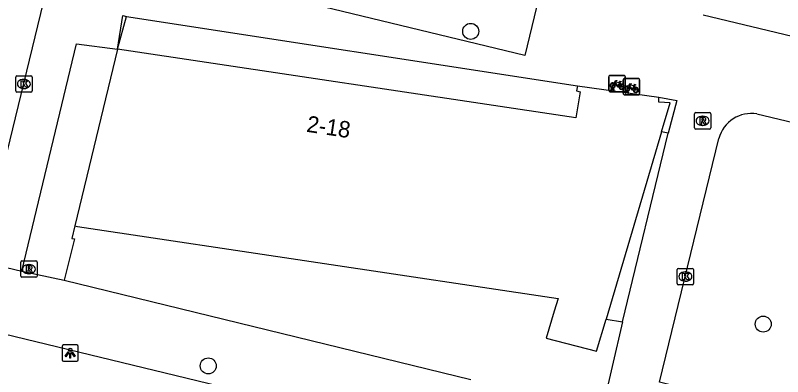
# Model space of a CAD drawing. Extents: x 162812 to 163818, y 381639 to 382470.
# Drawn here: x 163269.18 to 163316.1, y 382171.85 to 382193.93 of the extents above; entities that cross this region are included whole.
import ezdxf

# ---------------------------------------------------------------- set-up
doc = ezdxf.new("R2010")
doc.units = 0
for name, color, linetype in [('IMGEO_Boom', 7, 'Continuous'), ('IMGEO_Fietsenrek', 7, 'Continuous'), ('IMGEO_Groenvoorziening', 7, 'Continuous'), ('IMGEO_Kolk', 7, 'Continuous'), ('IMGEO_Lichtpunt', 7, 'Continuous'), ('IMGEO_Pand', 7, 'Continuous'), ('IMGEO_Pand_nummerreeks', 7, 'Continuous'), ('IMGEO_Pand_overbouw', 7, 'Continuous'), ('IMGEO_Rijbaan_lokaal_open', 7, 'Continuous'), ('IMGEO_Rioolput', 7, 'Continuous'), ('IMGEO_Voetpad_open', 7, 'Continuous')]:
    doc.layers.add(name, color=color, linetype=linetype)

msp = doc.modelspace()

# ---------------------------------------------------------------- linework, layer by layer
at = {"layer": 'IMGEO_Boom'}
for centre in [(163297.026, 382192.949), (163314.913, 382175.057), (163280.98, 382172.501)]:
    msp.add_circle(centre, 0.489, dxfattribs=at)
at = {"layer": 'IMGEO_Fietsenrek'}
for p, q in [((163305.476, 382189.335), (163305.476, 382190.176)), ((163305.476, 382190.176), (163305.476, 382189.335)), ((163305.551, 382190.26), (163306.392, 382190.26)), ((163306.392, 382190.26), (163305.551, 382190.26)), ((163306.433, 382190.066), (163307.274, 382190.066)), ((163307.274, 382190.066), (163306.433, 382190.066)), ((163306.476, 382190.185), (163306.476, 382189.344)), ((163306.476, 382189.344), (163306.476, 382190.185)), ((163306.163, 382189.809), (163306.199, 382189.714)), ((163306.358, 382189.141), (163306.358, 382189.982)), ((163306.358, 382189.982), (163306.358, 382189.141)), ((163307.045, 382189.615), (163307.081, 382189.52)), ((163307.358, 382189.991), (163307.358, 382189.15)), ((163307.358, 382189.15), (163307.358, 382189.991)), ((163306.401, 382189.26), (163305.56, 382189.26)), ((163305.56, 382189.26), (163306.401, 382189.26)), ((163305.603, 382189.344), (163305.642, 382189.504)), ((163305.637, 382189.344), (163305.603, 382189.344)), ((163305.672, 382189.492), (163305.637, 382189.344)), ((163305.714, 382189.516), (163305.713, 382189.52)), ((163305.755, 382189.344), (163305.721, 382189.486)), ((163305.745, 382189.527), (163305.746, 382189.52)), ((163305.753, 382189.49), (163305.788, 382189.344)), ((163305.788, 382189.344), (163305.755, 382189.344)), ((163306.485, 382189.15), (163306.524, 382189.31)), ((163306.519, 382189.15), (163306.485, 382189.15)), ((163306.554, 382189.298), (163306.519, 382189.15)), ((163306.596, 382189.322), (163306.595, 382189.326)), ((163306.637, 382189.15), (163306.603, 382189.292)), ((163306.627, 382189.333), (163306.628, 382189.326)), ((163306.635, 382189.296), (163306.67, 382189.15)), ((163306.67, 382189.15), (163306.637, 382189.15)), ((163307.283, 382189.066), (163306.442, 382189.066)), ((163306.442, 382189.066), (163307.283, 382189.066))]:
    msp.add_line(p, q, dxfattribs=at)
for points in [[(163305.81, 382189.734), (163305.758, 382189.644), (163305.718, 382189.619), (163305.719, 382189.666), (163305.774, 382189.76)], [(163305.789, 382189.786), (163305.884, 382189.95), (163305.97, 382189.936), (163305.972, 382189.927), (163305.916, 382189.916), (163305.889, 382189.871), (163306.145, 382189.83)], [(163306.085, 382189.542), (163306.035, 382189.542), (163305.844, 382189.793), (163305.825, 382189.761)], [(163306.132, 382189.805), (163305.875, 382189.846), (163305.858, 382189.817), (163306.025, 382189.597), (163306.132, 382189.805)], [(163306.18, 382189.707), (163306.15, 382189.784), (163306.041, 382189.566), (163306.084, 382189.566)], [(163306.114, 382189.566), (163306.234, 382189.565), (163306.19, 382189.679)], [(163306.21, 382189.686), (163306.265, 382189.541), (163306.115, 382189.541)], [(163306.145, 382189.83), (163306.17, 382189.879), (163306.164, 382189.883), (163306.141, 382189.887), (163306.129, 382189.894), (163306.128, 382189.897), (163306.13, 382189.902), (163306.225, 382189.887), (163306.227, 382189.877), (163306.217, 382189.864), (163306.205, 382189.858), (163306.191, 382189.864), (163306.163, 382189.809)], [(163306.692, 382189.54), (163306.64, 382189.45), (163306.6, 382189.425), (163306.601, 382189.472), (163306.656, 382189.566)], [(163306.671, 382189.592), (163306.766, 382189.756), (163306.852, 382189.742), (163306.854, 382189.733), (163306.798, 382189.722), (163306.771, 382189.677), (163307.027, 382189.636)], [(163306.967, 382189.348), (163306.917, 382189.348), (163306.726, 382189.599), (163306.707, 382189.567)], [(163307.014, 382189.611), (163306.757, 382189.652), (163306.74, 382189.623), (163306.907, 382189.403), (163307.014, 382189.611)], [(163307.062, 382189.513), (163307.032, 382189.59), (163306.923, 382189.372), (163306.966, 382189.372)], [(163307.027, 382189.636), (163307.052, 382189.685), (163307.046, 382189.689), (163307.023, 382189.693), (163307.011, 382189.7), (163307.01, 382189.703), (163307.012, 382189.708), (163307.107, 382189.693), (163307.109, 382189.683), (163307.099, 382189.67), (163307.087, 382189.664), (163307.073, 382189.67), (163307.045, 382189.615)], [(163306.996, 382189.372), (163307.116, 382189.371), (163307.072, 382189.485)], [(163307.092, 382189.492), (163307.147, 382189.347), (163306.997, 382189.347)]]:
    msp.add_lwpolyline(points, dxfattribs=at)
for centre, radius, start, end in [((163305.554, 382190.182), 0.0779, 92.4484, 184.2845), ((163305.554, 382190.182), 0.0779, 92.4484, 184.2845), ((163306.436, 382189.988), 0.0779, 92.4484, 184.2845), ((163306.436, 382189.988), 0.0779, 92.4484, 184.2845), ((163306.398, 382190.182), 0.0779, 2.4484, 94.2845), ((163306.398, 382190.182), 0.0779, 2.4484, 94.2845), ((163307.28, 382189.988), 0.0779, 2.4484, 94.2845), ((163307.28, 382189.988), 0.0779, 2.4484, 94.2845), ((163305.716, 382189.645), 0.159, 62.6766, 242.1369), ((163305.716, 382189.645), 0.129, 63.3192, 238.903), ((163305.696, 382189.516), 0.0499, 12.8025, 158.6934), ((163305.716, 382189.645), 0.129, 283.6043, 43.4302), ((163305.716, 382189.645), 0.159, 283.5766, 46.6042), ((163306.243, 382189.561), 0.159, 113.3408, 178.3217), ((163306.243, 382189.561), 0.159, 187.0065, 105.7708), ((163306.243, 382189.561), 0.129, 113.923, 177.9556), ((163306.243, 382189.561), 0.129, 188.6715, 104.5883), ((163306.598, 382189.451), 0.159, 62.6766, 242.1369), ((163306.598, 382189.451), 0.129, 63.3192, 238.903), ((163306.598, 382189.451), 0.129, 283.6043, 43.4302), ((163306.598, 382189.451), 0.159, 283.5766, 46.6042), ((163305.554, 382189.338), 0.0779, 182.4484, 274.2845), ((163305.554, 382189.338), 0.0779, 182.4484, 274.2845), ((163305.716, 382189.645), 0.159, 253.9967, 271.7867), ((163305.696, 382189.516), 0.0174, 12.8025, 163.4502), ((163305.716, 382189.645), 0.129, 253.415, 269.0204), ((163306.436, 382189.144), 0.0779, 182.4484, 274.2845), ((163306.436, 382189.144), 0.0779, 182.4484, 274.2845), ((163306.398, 382189.338), 0.0779, 272.4484, 4.2845), ((163306.398, 382189.338), 0.0779, 272.4484, 4.2845), ((163306.578, 382189.322), 0.0499, 12.8025, 158.6934), ((163306.598, 382189.451), 0.159, 253.9967, 271.7867), ((163306.578, 382189.322), 0.0174, 12.8025, 163.4502), ((163306.598, 382189.451), 0.129, 253.415, 269.0204), ((163307.125, 382189.367), 0.159, 113.3408, 178.3217), ((163307.125, 382189.367), 0.159, 187.0065, 105.7708), ((163307.125, 382189.367), 0.129, 113.923, 177.9556), ((163307.125, 382189.367), 0.129, 188.6715, 104.5883), ((163307.28, 382189.144), 0.0779, 272.4484, 4.2845), ((163307.28, 382189.144), 0.0779, 272.4484, 4.2845)]:
    msp.add_arc(centre, radius, start, end, dxfattribs=at)
at = {"layer": 'IMGEO_Groenvoorziening'}
for points in [[(163272.811, 382181.055), (163272.627, 382180.291), (163272.792, 382180.266), (163272.171, 382177.751)], [(163269.579, 382178.285), (163272.171, 382177.751)], [(163272.171, 382177.751), (163297.042, 382171.68)]]:
    msp.add_lwpolyline(points, dxfattribs=at)
at = {"layer": 'IMGEO_Kolk'}
for p, q in [((163269.206, 382189.307), (163269.206, 382190.159)), ((163269.281, 382190.233), (163270.133, 382190.233)), ((163269.694, 382190.013), (163269.719, 382190.013)), ((163270.207, 382190.159), (163270.207, 382189.307)), ((163270.133, 382189.233), (163269.281, 382189.233)), ((163269.717, 382189.453), (163269.692, 382189.453)), ((163309.651, 382177.536), (163309.651, 382178.388)), ((163309.726, 382178.462), (163310.578, 382178.462)), ((163310.652, 382178.388), (163310.652, 382177.536)), ((163310.139, 382178.242), (163310.164, 382178.242)), ((163310.578, 382177.462), (163309.726, 382177.462)), ((163310.162, 382177.682), (163310.137, 382177.682))]:
    msp.add_line(p, q, dxfattribs=at)
for points in [[(163269.206, 382189.307), (163269.206, 382190.159)], [(163269.281, 382190.233), (163270.133, 382190.233)], [(163270.207, 382190.159), (163270.207, 382189.307)], [(163269.527, 382189.933), (163269.65, 382189.933), (163269.65, 382189.782), (163269.78, 382189.933), (163269.944, 382189.933), (163269.798, 382189.782), (163269.951, 382189.533), (163269.799, 382189.533), (163269.714, 382189.697), (163269.65, 382189.63), (163269.65, 382189.533), (163269.527, 382189.533), (163269.527, 382189.933)], [(163270.133, 382189.233), (163269.281, 382189.233)], [(163309.651, 382177.536), (163309.651, 382178.388)], [(163309.726, 382178.462), (163310.578, 382178.462)], [(163310.652, 382178.388), (163310.652, 382177.536)], [(163309.972, 382178.162), (163310.095, 382178.162), (163310.095, 382178.011), (163310.225, 382178.162), (163310.389, 382178.162), (163310.243, 382178.011), (163310.396, 382177.762), (163310.244, 382177.762), (163310.159, 382177.926), (163310.095, 382177.859), (163310.095, 382177.762), (163309.972, 382177.762), (163309.972, 382178.162)], [(163310.578, 382177.462), (163309.726, 382177.462)]]:
    msp.add_lwpolyline(points, dxfattribs=at)
for centre, start, end in [((163269.283, 382190.157), 91.552, 178.448), ((163269.283, 382190.157), 91.552, 178.448), ((163270.131, 382190.157), 1.552, 88.448), ((163270.131, 382190.157), 1.552, 88.448), ((163269.283, 382189.309), 181.552, 268.448), ((163269.283, 382189.309), 181.552, 268.448), ((163270.131, 382189.309), 271.552, 358.448), ((163270.131, 382189.309), 271.552, 358.448), ((163309.728, 382178.386), 91.552, 178.448), ((163309.728, 382178.386), 91.552, 178.448), ((163310.576, 382178.386), 1.552, 88.448), ((163310.576, 382178.386), 1.552, 88.448), ((163309.728, 382177.538), 181.552, 268.448), ((163309.728, 382177.538), 181.552, 268.448), ((163310.576, 382177.538), 271.552, 358.448), ((163310.576, 382177.538), 271.552, 358.448)]:
    msp.add_arc(centre, 0.0765, start, end, dxfattribs=at)
for centre, major_axis, ratio, start_param, end_param in [((163269.693, 382189.733), (-0.387, 0.002), 0.722429, 4.712389, 7.853982), ((163269.718, 382189.733), (-0.39, 0.002), 0.717154, 1.570796, 4.712389), ((163310.138, 382177.962), (-0.387, 0.002), 0.722429, 4.712389, 7.853982), ((163310.163, 382177.962), (-0.39, 0.002), 0.717154, 1.570796, 4.712389)]:
    msp.add_ellipse(centre, major_axis=major_axis, ratio=ratio, start_param=start_param, end_param=end_param, dxfattribs=at)
at = {"layer": 'IMGEO_Lichtpunt'}
for p, q in [((163272.036, 382173.69), (163272.036, 382172.883)), ((163272.036, 382173.69), (163272.036, 382172.883)), ((163272.938, 382173.785), (163272.13, 382173.785)), ((163272.938, 382173.785), (163272.13, 382173.785)), ((163273.032, 382172.883), (163273.032, 382173.69)), ((163273.032, 382172.883), (163273.032, 382173.69)), ((163272.13, 382172.789), (163272.938, 382172.789)), ((163272.13, 382172.789), (163272.938, 382172.789))]:
    msp.add_line(p, q, dxfattribs=at)
for points in [[(163272.41, 382173.354), (163272.449, 382173.326), (163272.261, 382173.064), (163272.223, 382173.091), (163272.41, 382173.354)], [(163272.512, 382173.306), (163272.559, 382173.306), (163272.559, 382172.984), (163272.512, 382172.984), (163272.512, 382173.306)], [(163272.622, 382173.326), (163272.66, 382173.353), (163272.847, 382173.091), (163272.808, 382173.063), (163272.622, 382173.326)]]:
    msp.add_lwpolyline(points, dxfattribs=at)
msp.add_circle((163272.535, 382173.488), 0.0994, dxfattribs=at)
for centre, start, end in [((163272.13, 382173.69), 90, 180), ((163272.13, 382173.69), 90, 180), ((163272.938, 382173.69), 0, 90), ((163272.938, 382173.69), 0, 90), ((163272.13, 382172.883), 180, 270), ((163272.13, 382172.883), 180, 270), ((163272.938, 382172.883), 270, 0), ((163272.938, 382172.883), 270, 360)]:
    msp.add_arc(centre, 0.0946, start, end, dxfattribs=at)
at = {"layer": 'IMGEO_Pand'}
for points in [[(163275.427, 382191.863), (163272.811, 382181.055)], [(163303.556, 382189.624), (163303.504, 382189.319), (163303.712, 382189.26), (163303.455, 382187.657), (163275.427, 382191.863)], [(163303.556, 382189.624), (163308.534, 382188.925)], [(163308.701, 382186.815), (163309.223, 382188.572), (163308.524, 382188.631), (163308.534, 382188.925)], [(163308.701, 382186.815), (163305.301, 382175.36)], [(163272.811, 382181.055), (163272.981, 382181.029), (163302.37, 382176.619), (163302.138, 382175.838), (163301.65, 382174.195), (163304.723, 382173.413), (163305.301, 382175.36)]]:
    msp.add_lwpolyline(points, dxfattribs=at)
at = {"layer": 'IMGEO_Pand_overbouw'}
msp.add_lwpolyline([(163305.301, 382175.36), (163306.317, 382175.199), (163309.096, 382186.726), (163308.701, 382186.815)], close=True, dxfattribs=at)
at = {"layer": 'IMGEO_Rijbaan_lokaal_open'}
msp.add_lwpolyline([(163327.147, 382190.126), (163311.244, 382193.937)], dxfattribs=at)
at = {"layer": 'IMGEO_Rioolput'}
for p, q in [((163310.708, 382187.055), (163310.708, 382187.907)), ((163310.783, 382187.981), (163311.635, 382187.981)), ((163311.196, 382187.761), (163311.221, 382187.761)), ((163311.709, 382187.907), (163311.709, 382187.055)), ((163311.219, 382187.201), (163311.194, 382187.201)), ((163311.635, 382186.981), (163310.783, 382186.981)), ((163269.51, 382177.991), (163269.51, 382178.843)), ((163269.585, 382178.917), (163270.437, 382178.917)), ((163270.511, 382178.843), (163270.511, 382177.991)), ((163269.998, 382178.697), (163270.023, 382178.697)), ((163270.437, 382177.917), (163269.585, 382177.917)), ((163270.021, 382178.137), (163269.996, 382178.137))]:
    msp.add_line(p, q, dxfattribs=at)
for points in [[(163310.708, 382187.055), (163310.708, 382187.907)], [(163310.783, 382187.981), (163311.635, 382187.981)], [(163311.297, 382187.679), (163311.045, 382187.681), (163311.045, 382187.281)], [(163311.709, 382187.907), (163311.709, 382187.055)], [(163311.045, 382187.281), (163311.169, 382187.281), (163311.169, 382187.443), (163311.18, 382187.443)], [(163311.223, 382187.6), (163311.169, 382187.6), (163311.169, 382187.519)], [(163311.169, 382187.519), (163311.221, 382187.519)], [(163311.227, 382187.414), (163311.298, 382187.281), (163311.438, 382187.281), (163311.373, 382187.407)], [(163311.635, 382186.981), (163310.783, 382186.981)], [(163269.51, 382177.991), (163269.51, 382178.843)], [(163269.585, 382178.917), (163270.437, 382178.917)], [(163270.511, 382178.843), (163270.511, 382177.991)], [(163270.099, 382178.615), (163269.847, 382178.617), (163269.847, 382178.217)], [(163269.847, 382178.217), (163269.971, 382178.217), (163269.971, 382178.379), (163269.982, 382178.379)], [(163270.025, 382178.536), (163269.971, 382178.536), (163269.971, 382178.455)], [(163269.971, 382178.455), (163270.023, 382178.455)], [(163270.029, 382178.35), (163270.1, 382178.217), (163270.24, 382178.217), (163270.175, 382178.343)], [(163270.437, 382177.917), (163269.585, 382177.917)]]:
    msp.add_lwpolyline(points, dxfattribs=at)
for centre, radius, start, end in [((163310.785, 382187.905), 0.0765, 91.552, 178.448), ((163310.785, 382187.905), 0.0765, 91.552, 178.448), ((163311.296, 382187.569), 0.109, 350.3612, 89.416), ((163311.633, 382187.905), 0.0765, 1.552, 88.448), ((163311.633, 382187.905), 0.0765, 1.552, 88.448), ((163311.179, 382187.39), 0.0533, 26.0293, 88.6989), ((163311.205, 382187.708), 0.19, 274.7715, 282.9687), ((163311.229, 382187.504), 0.0964, 77.0061, 93.1865), ((163311.243, 382187.561), 0.0378, 276.6634, 79.6772), ((163311.294, 382187.569), 0.112, 277.5842, 350.9817), ((163311.278, 382187.354), 0.108, 29.5134, 73.7905), ((163310.785, 382187.057), 0.0765, 181.552, 268.448), ((163310.785, 382187.057), 0.0765, 181.552, 268.448), ((163311.633, 382187.057), 0.0765, 271.552, 358.448), ((163311.633, 382187.057), 0.0765, 271.552, 358.448), ((163269.587, 382178.841), 0.0765, 91.552, 178.448), ((163269.587, 382178.841), 0.0765, 91.552, 178.448), ((163270.435, 382178.841), 0.0765, 1.552, 88.448), ((163270.435, 382178.841), 0.0765, 1.552, 88.448), ((163269.981, 382178.326), 0.0533, 26.0293, 88.6989), ((163270.007, 382178.644), 0.19, 274.7715, 282.9687), ((163270.031, 382178.44), 0.0964, 77.0061, 93.1865), ((163270.045, 382178.497), 0.0378, 276.6634, 79.6772), ((163270.098, 382178.505), 0.109, 350.3612, 89.416), ((163270.096, 382178.505), 0.112, 277.5842, 350.9817), ((163270.08, 382178.29), 0.108, 29.5134, 73.7905), ((163269.587, 382177.993), 0.0765, 181.552, 268.448), ((163269.587, 382177.993), 0.0765, 181.552, 268.448), ((163270.435, 382177.993), 0.0765, 271.552, 358.448), ((163270.435, 382177.993), 0.0765, 271.552, 358.448)]:
    msp.add_arc(centre, radius, start, end, dxfattribs=at)
for centre, major_axis, ratio, start_param, end_param in [((163311.195, 382187.481), (-0.387, 0.002), 0.722429, 4.712389, 7.853982), ((163311.22, 382187.481), (-0.39, 0.002), 0.717154, 1.570796, 4.712389), ((163269.997, 382178.417), (-0.387, 0.002), 0.722429, 4.712389, 7.853982), ((163270.022, 382178.417), (-0.39, 0.002), 0.717154, 1.570796, 4.712389)]:
    msp.add_ellipse(centre, major_axis=major_axis, ratio=ratio, start_param=start_param, end_param=end_param, dxfattribs=at)
at = {"layer": 'IMGEO_Voetpad_open'}
for points in [[(163301.055, 382194.434), (163300.335, 382191.472), (163276.941, 382197.127), (163277.641, 382200.072)], [(163270.876, 382194.712), (163268.502, 382184.903)], [(163275.427, 382191.863), (163275.745, 382193.917), (163275.974, 382193.848)], [(163275.427, 382191.863), (163275.974, 382193.848)], [(163275.974, 382193.848), (163303.556, 382189.624)], [(163269.579, 382178.285), (163272.912, 382192.189), (163275.427, 382191.863)], [(163308.534, 382188.925), (163309.631, 382188.717), (163309.096, 382186.726), (163308.701, 382186.815)], [(163314.533, 382187.899), (163320.851, 382186.391)], [(163322.331, 382183.982), (163318.73, 382169.011), (163308.573, 382171.509), (163312.197, 382186.407)], [(163263.175, 382175.728), (163264.11, 382179.591), (163269.579, 382178.285)], [(163296.089, 382167.75), (163263.175, 382175.728)], [(163305.301, 382175.36), (163306.317, 382175.199), (163305.036, 382169.729)]]:
    msp.add_lwpolyline(points, dxfattribs=at)
msp.add_arc((163314.184, 382185.87), 2.058, 80.2429, 164.8898, dxfattribs=at)

# ---------------------------------------------------------------- texts
at = {"layer": 'IMGEO_Pand_nummerreeks'}
msp.add_text('2-18', height=1, rotation=351.4656, dxfattribs=at).set_placement((163286.947, 382186.817))

doc.saveas('drawing.dxf')
